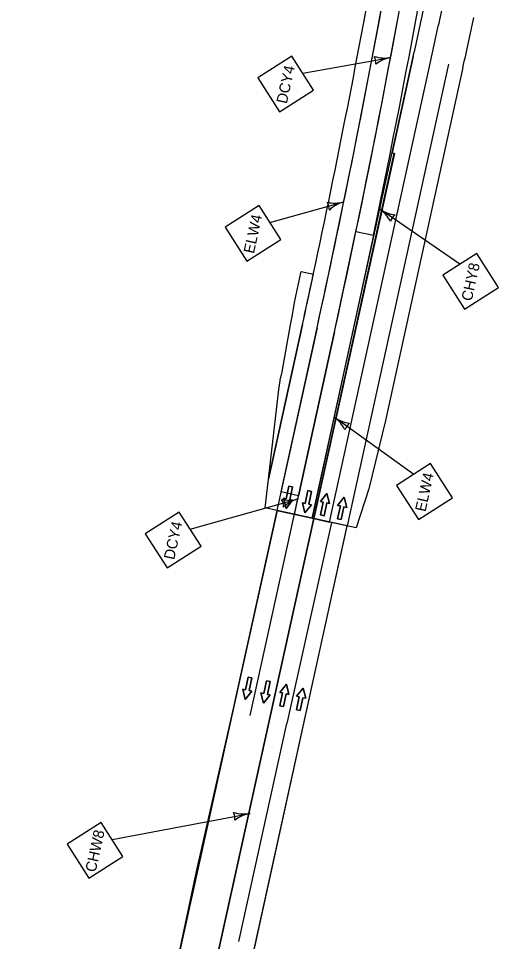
# Model space of a CAD drawing. Extents: x 14104283 to 14128447, y 8633203 to 8671666.
# Drawn here: x 14107609 to 14107930, y 8638776 to 8639393 of the extents above; entities that cross this region are included whole.
import ezdxf

# ---------------------------------------------------------------- set-up
doc = ezdxf.new("R2010")
doc.units = 0
for name, color, linetype in [('Cell', 7, 'Continuous'), ('Default', 7, 'Continuous'), ('dsnPaintExistingBrokenLaneLineWhite', 7, 'Continuous'), ('dsnPaintExistingEdgeLineRightWhite', 7, 'Continuous'), ('dsnPaintPlaceBrokenLineWhite', 7, 'Continuous'), ('dsnPaintPlaceEdgeLineRightWhite', 7, 'Continuous'), ('dsnStdLabel', 7, 'Continuous'), ('dsnStgShadingPrevPav', 7, 'Continuous')]:
    doc.layers.add(name, color=color, linetype=linetype)

msp = doc.modelspace()

# ---------------------------------------------------------------- linework, layer by layer
at = {"layer": 'Cell'}
for points in [[(14107789.7, 8639080.29), (14107792.14, 8639079.75), (14107790.27, 8639071.21), (14107792.11, 8639070.81), (14107787.72, 8639065.37), (14107786, 8639072.14), (14107787.83, 8639071.74)], [(14107802.35, 8639077.26), (14107804.79, 8639076.73), (14107802.93, 8639068.18), (14107804.76, 8639067.78), (14107800.38, 8639062.34), (14107798.65, 8639069.11), (14107800.49, 8639068.71)], [(14107813.13, 8639060.49), (14107810.69, 8639061.02), (14107812.55, 8639069.57), (14107810.72, 8639069.97), (14107815.11, 8639075.41), (14107816.83, 8639068.64), (14107815, 8639069.04)], [(14107824.64, 8639057.94), (14107822.2, 8639058.47), (14107824.06, 8639067.02), (14107822.23, 8639067.42), (14107826.62, 8639072.86), (14107828.34, 8639066.09), (14107826.5, 8639066.49)], [(14107762.48, 8638952.74), (14107764.92, 8638952.21), (14107763.06, 8638943.66), (14107764.89, 8638943.26), (14107760.5, 8638937.82), (14107758.78, 8638944.6), (14107760.62, 8638944.2)], [(14107774.67, 8638950.27), (14107777.11, 8638949.74), (14107775.24, 8638941.19), (14107777.08, 8638940.79), (14107772.69, 8638935.35), (14107770.97, 8638942.13), (14107772.8, 8638941.73)], [(14107786.01, 8638933.02), (14107783.57, 8638933.55), (14107785.43, 8638942.1), (14107783.6, 8638942.5), (14107787.99, 8638947.94), (14107789.71, 8638941.17), (14107787.87, 8638941.57)], [(14107797.19, 8638930.4), (14107794.75, 8638930.93), (14107796.62, 8638939.48), (14107794.78, 8638939.88), (14107799.17, 8638945.32), (14107800.89, 8638938.55), (14107799.06, 8638938.95)]]:
    msp.add_lwpolyline(points, close=True, dxfattribs=at)
for points in [[(14107787.83, 8639071.74), (14107786, 8639072.14), (14107787.72, 8639065.37), (14107792.11, 8639070.81), (14107790.27, 8639071.21), (14107792.14, 8639079.75), (14107789.7, 8639080.29), (14107787.83, 8639071.74)], [(14107800.49, 8639068.71), (14107798.65, 8639069.11), (14107800.38, 8639062.34), (14107804.76, 8639067.78), (14107802.93, 8639068.18), (14107804.79, 8639076.73), (14107802.35, 8639077.26), (14107800.49, 8639068.71)], [(14107815, 8639069.04), (14107816.83, 8639068.64), (14107815.11, 8639075.41), (14107810.72, 8639069.97), (14107812.55, 8639069.57), (14107810.69, 8639061.02), (14107813.13, 8639060.49), (14107815, 8639069.04)], [(14107826.5, 8639066.49), (14107828.34, 8639066.09), (14107826.62, 8639072.86), (14107822.23, 8639067.42), (14107824.06, 8639067.02), (14107822.2, 8639058.47), (14107824.64, 8639057.94), (14107826.5, 8639066.49)], [(14107760.62, 8638944.2), (14107758.78, 8638944.6), (14107760.5, 8638937.82), (14107764.89, 8638943.26), (14107763.06, 8638943.66), (14107764.92, 8638952.21), (14107762.48, 8638952.74), (14107760.62, 8638944.2)], [(14107772.8, 8638941.73), (14107770.97, 8638942.13), (14107772.69, 8638935.35), (14107777.08, 8638940.79), (14107775.24, 8638941.19), (14107777.11, 8638949.74), (14107774.67, 8638950.27), (14107772.8, 8638941.73)], [(14107787.87, 8638941.57), (14107789.71, 8638941.17), (14107787.99, 8638947.94), (14107783.6, 8638942.5), (14107785.43, 8638942.1), (14107783.57, 8638933.55), (14107786.01, 8638933.02), (14107787.87, 8638941.57)], [(14107799.06, 8638938.95), (14107800.89, 8638938.55), (14107799.17, 8638945.32), (14107794.78, 8638939.88), (14107796.62, 8638939.48), (14107794.75, 8638930.93), (14107797.19, 8638930.4), (14107799.06, 8638938.95)]]:
    msp.add_lwpolyline(points, dxfattribs=at)
at = {"layer": 'Default'}
for p, q in [((14107805.11, 8639058.86), (14107872.86, 8639367.26)), ((14107896.3, 8639362.11), (14107828.56, 8639053.71)), ((14107834.52, 8639250.33), (14107846.27, 8639247.88)), ((14107784.41, 8639076.47), (14107808.47, 8639186.01)), ((14107820.2, 8639183.44), (14107796.13, 8639073.89)), ((14107796.13, 8639073.89), (14107784.41, 8639076.47)), ((14107781.69, 8639064), (14107653.91, 8638485.4)), ((14107806.31, 8639058.6), (14107781.69, 8639064)), ((14107678.52, 8638479.96), (14107806.31, 8639058.6)), ((14107828.56, 8639053.71), (14107805.11, 8639058.86))]:
    msp.add_line(p, q, dxfattribs=at)
for points in [[(14107793.39, 8639061.43), (14107820.2, 8639183.44), (14107834.52, 8639250.33), (14107846.27, 8639247.88), (14107805.11, 8639058.86)], [(14107649.23, 8638236.01), (14107828.56, 8639053.71), (14107806.31, 8639058.6), (14107625.69, 8638240.73)]]:
    msp.add_lwpolyline(points, close=True, dxfattribs=at)
for centre, radius, start, end in [((14101471.58, 8640578.08), 6488, 347.610212, 351.325989), ((14101471.58, 8640578.08), 6500, 347.610212, 351.325989), ((14101471.58, 8640578.08), 6500, 348.213241, 351.325989), ((14101471.58, 8640578.08), 6512, 348.213241, 351.325989), ((14089678.7, 8643364.11), 18628, 347.610212, 347.714933)]:
    msp.add_arc(centre, radius, start, end, dxfattribs=at)
at = {"layer": 'dsnPaintExistingBrokenLaneLineWhite'}
for p in [(14107818.04, 8639056.04), (14107756.2, 8638776.05)]:
    msp.add_line(p, (14107788.37, 8638921.68), dxfattribs=at)
at = {"layer": 'dsnPaintExistingEdgeLineRightWhite'}
for p, q in [((14107781.67, 8639064.01), (14107752.01, 8638929.68)), ((14107468.79, 8637415.99), (14107828.52, 8639053.57))]:
    msp.add_line(p, q, dxfattribs=at)
msp.add_lwpolyline([(14107752.01, 8638929.68), (14107727.67, 8638822.93), (14107708.89, 8638734.37)], dxfattribs=at)
at = {"layer": 'dsnPaintPlaceBrokenLineWhite'}
for p, q in [((14107796.13, 8639073.89), (14107820.2, 8639183.44)), ((14107763.69, 8638926.99), (14107796.13, 8639073.89))]:
    msp.add_line(p, q, dxfattribs=at)
msp.add_arc((14101471.58, 8640578.08), 6500, 347.610212, 351.325989, dxfattribs=at)
at = {"layer": 'dsnPaintPlaceEdgeLineRightWhite'}
msp.add_line((14107808.47, 8639186.01), (14107781.67, 8639064.01), dxfattribs=at)
msp.add_arc((14101471.58, 8640578.08), 6488, 347.610212, 351.325989, dxfattribs=at)
at = {"layer": 'dsnStdLabel'}
for p, q in [((14107798.89, 8639356.26), (14107857.88, 8639366.61)), ((14107776.96, 8639256.43), (14107826.39, 8639270.21)), ((14107903.96, 8639228.52), (14107850.2, 8639265.48)), ((14107873.1, 8639088.04), (14107819.95, 8639126.4)), ((14107723.58, 8639051.62), (14107795.82, 8639071.76)), ((14107671.34, 8638844.28), (14107763.63, 8638861.67))]:
    msp.add_line(p, q, dxfattribs=at)
for points in [[(14107783.42, 8639330.34), (14107806.17, 8639344.89), (14107791.62, 8639367.63), (14107768.87, 8639353.08)], [(14107761.49, 8639230.51), (14107784.23, 8639245.06), (14107769.68, 8639267.8), (14107746.94, 8639253.25)], [(14107907.14, 8639198.51), (14107929.88, 8639213.05), (14107915.33, 8639235.8), (14107892.59, 8639221.25)], [(14107876.27, 8639058.02), (14107899.02, 8639072.57), (14107884.47, 8639095.32), (14107861.72, 8639080.77)], [(14107708.11, 8639025.7), (14107730.86, 8639040.25), (14107716.31, 8639063), (14107693.56, 8639048.45)], [(14107655.87, 8638818.36), (14107678.62, 8638832.91), (14107664.07, 8638855.66), (14107641.32, 8638841.11)]]:
    msp.add_lwpolyline(points, close=True, dxfattribs=at)
for centre, radius, start, end in [((14107853.91, 8639389.22), 22.95, 251.88434, 279.95564), ((14107838.93, 8639363.29), 8.86, 352.22132, 27.68977), ((14107861.85, 8639344.01), 22.95, 99.95549, 128.02676), ((14107820.22, 8639292.31), 22.95, 257.50319, 285.5745), ((14107807.85, 8639265.04), 8.86, 357.84017, 33.30862), ((14107832.55, 8639248.1), 22.95, 105.57434, 133.64561), ((14107837.2, 8639246.56), 22.95, 27.42577, 55.49708), ((14107863.2, 8639284.39), 22.95, 235.49693, 263.56819), ((14107866.06, 8639254.58), 8.86, 127.76276, 163.23121), ((14107806.52, 8639107.79), 22.95, 26.10673, 54.17804), ((14107833.38, 8639145.01), 22.95, 234.17788, 262.24915), ((14107835.55, 8639115.14), 8.86, 126.44371, 161.91216), ((14107789.66, 8639093.87), 22.95, 257.50319, 285.5745), ((14107777.28, 8639066.59), 8.86, 357.84017, 33.30862), ((14107801.98, 8639049.65), 22.95, 105.57434, 133.64561), ((14107759.38, 8638884.22), 22.95, 252.59767, 280.66897), ((14107744.72, 8638858.11), 8.86, 352.93465, 28.4031), ((14107767.88, 8638839.12), 22.95, 100.66882, 128.74009)]:
    msp.add_arc(centre, radius, start, end, dxfattribs=at)
at = {"layer": 'dsnStgShadingPrevPav'}
for p, q in [((14107816.84, 8639056.28), (14107884.58, 8639364.69)), ((14107816.84, 8639056.28), (14107884.58, 8639364.69)), ((14107858.72, 8639302.86), (14107872.86, 8639367.26)), ((14107872.86, 8639367.26), (14107858.72, 8639302.86)), ((14107906.07, 8639359.97), (14107854.27, 8639124.15)), ((14107806.3, 8639058.6), (14107860.16, 8639302.55)), ((14107860.17, 8639302.55), (14107806.31, 8639058.6)), ((14107860.16, 8639302.55), (14107858.72, 8639302.86)), ((14107858.81, 8639302.85), (14107860.17, 8639302.55)), ((14107808.47, 8639186.01), (14107781.67, 8639064.01)), ((14107854.27, 8639124.15), (14107843.05, 8639078.38)), ((14107843.05, 8639078.38), (14107834.68, 8639052.36)), ((14107781.67, 8639064.01), (14107806.3, 8639058.6)), ((14107806.31, 8639058.6), (14107816.84, 8639056.28)), ((14107834.68, 8639052.36), (14107816.84, 8639056.28))]:
    msp.add_line(p, q, dxfattribs=at)
for points in [[(14107798.71, 8639188.16), (14107776.02, 8639084.89), (14107783.02, 8639144.91), (14107783.81, 8639150.65), (14107783.9, 8639151.14), (14107785.2, 8639156.75), (14107790.77, 8639188.01), (14107791.75, 8639193.68), (14107793.6, 8639204.06), (14107797.89, 8639223.6), (14107806.01, 8639221.81)], [(14107808.47, 8639186.01), (14107781.67, 8639064.01), (14107773.79, 8639065.74), (14107776.02, 8639084.89), (14107798.71, 8639188.16)]]:
    msp.add_lwpolyline(points, dxfattribs=at)
for centre, radius, start, end in [((14101471.58, 8640578.08), 6478, 347.610212, 349.599496), ((14101471.57, 8640578.08), 6488, 347.610212, 349.596428), ((14101471.58, 8640578.08), 6488, 347.610212, 349.596429), ((14089678.7, 8643364.11), 18628, 347.610212, 347.714997), ((14089678.7, 8643364.11), 18628, 347.610212, 347.714997), ((14089678.7, 8643364.11), 18640, 347.610212, 347.714997), ((14089678.7, 8643364.11), 18640, 347.610212, 347.714933), ((14089678.7, 8643364.11), 18662, 347.610212, 347.714933), ((14101471.58, 8640578.08), 6478, 347.888031, 347.914808), ((14101471.58, 8640578.08), 6478, 347.610212, 347.888031)]:
    msp.add_arc(centre, radius, start, end, dxfattribs=at)

# ---------------------------------------------------------------- texts
at = {"layer": 'dsnStdLabel'}
for s, p in [('DCY4', (14107788.21, 8639335.35)), ('ELW4', (14107766.22, 8639235.24)), ('CHY8', (14107911.92, 8639203.49)), ('ELW4', (14107881, 8639062.76)), ('DCY4', (14107712.9, 8639030.71)), ('CHW8', (14107660.35, 8638821.99))]:
    msp.add_text(s, height=7.2, rotation=77.60784, dxfattribs=at).set_placement(p)

doc.saveas('drawing.dxf')
